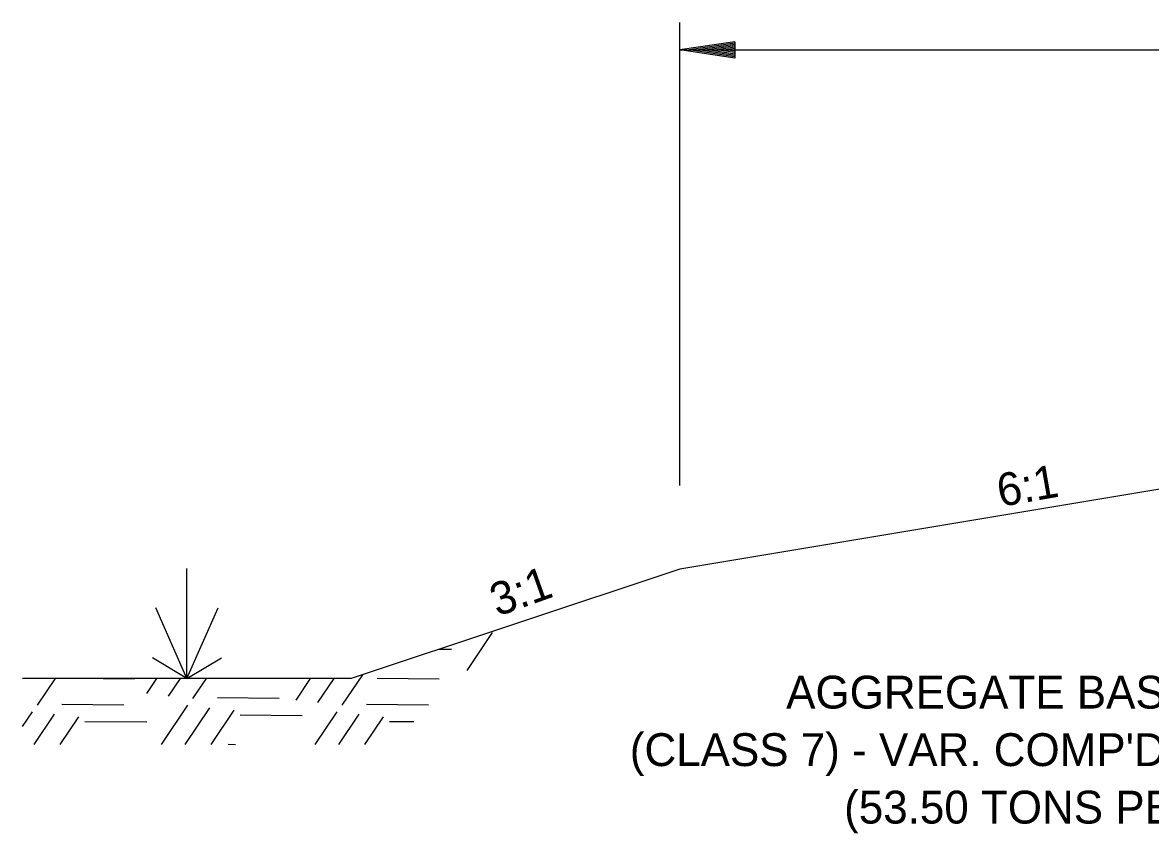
# Model space of a CAD drawing. Extents: x -900 to 15312, y 1857 to 2945.
# Drawn here: x 3634.2 to 3840, y 2382.9 to 2531 of the extents above; entities that cross this region are included whole.
import ezdxf

# ---------------------------------------------------------------- set-up
doc = ezdxf.new("R2010")
doc.units = 0
for name, color, linetype in [('R_Annotation', 7, 'Continuous'), ('R_Dimension', 7, 'Continuous'), ('R_Draft', 7, 'Continuous')]:
    doc.layers.add(name, color=color, linetype=linetype)

msp = doc.modelspace()

# ---------------------------------------------------------------- linework, layer by layer
at = {"layer": 'R_Annotation'}
for p, q in [((3914.16, 2457.89), (3754.16, 2431.22)), ((3754.16, 2431.22), (3694.16, 2411.22)), ((3694.16, 2411.22), (3634.16, 2411.22))]:
    msp.add_line(p, q, dxfattribs=at)
at = {"layer": 'R_Dimension'}
for p, q in [((3754.16, 2446.49), (3754.16, 2531.02)), ((3764.16, 2527.52), (3754.16, 2526.02)), ((3764.16, 2527.27), (3755.83, 2526.02)), ((3764.16, 2527.02), (3757.55, 2526.02)), ((3764.16, 2526.77), (3759.21, 2526.02)), ((3764.16, 2526.51), (3760.91, 2526.02)), ((3764.16, 2526.26), (3762.58, 2526.02)), ((3764.16, 2527.52), (3764.16, 2524.52)), ((3764.16, 2524.52), (3754.16, 2526.02)), ((3754.16, 2526.02), (3954.16, 2526.02)), ((3764.16, 2524.77), (3755.83, 2526.02)), ((3764.16, 2525.03), (3757.55, 2526.02)), ((3764.16, 2525.28), (3759.21, 2526.02)), ((3764.16, 2525.53), (3760.91, 2526.02)), ((3764.16, 2525.79), (3762.58, 2526.02)), ((3715.3, 2412.7), (3719.96, 2419.62)), ((3710.21, 2416.57), (3712.45, 2416.56)), ((3636.9, 2406.35), (3640.19, 2411.22)), ((3648.87, 2411.22), (3654.61, 2411.18)), ((3656.83, 2408.49), (3658.68, 2411.22)), ((3660.82, 2408.02), (3662.98, 2411.22)), ((3665.27, 2407.56), (3667.74, 2411.22)), ((3684.09, 2407.28), (3686.75, 2411.22)), ((3688.07, 2406.82), (3691.05, 2411.22)), ((3692.52, 2406.35), (3696.29, 2411.93)), ((3698.92, 2411.27), (3710.23, 2411.18)), ((3669.72, 2407.75), (3681.03, 2407.65)), ((3634.16, 2402.46), (3635.98, 2405.15)), ((3641.35, 2406.54), (3652.66, 2406.45)), ((3659.52, 2399.2), (3664.34, 2406.35)), ((3663.82, 2399.2), (3668.33, 2405.89)), ((3668.58, 2399.2), (3672.78, 2405.43)), ((3687.58, 2399.2), (3691.6, 2405.15)), ((3696.97, 2406.54), (3708.28, 2406.45)), ((3636.26, 2399.2), (3639.96, 2404.69)), ((3641.03, 2399.2), (3644.41, 2404.22)), ((3645.52, 2403.39), (3656.83, 2403.29)), ((3673.89, 2404.59), (3685.2, 2404.5)), ((3691.88, 2399.2), (3695.58, 2404.69)), ((3696.65, 2399.2), (3700.03, 2404.22)), ((3701.14, 2403.39), (3705.57, 2403.35)), ((3671.67, 2399.21), (3673.02, 2399.2))]:
    msp.add_line(p, q, dxfattribs=at)
at = {"layer": 'R_Draft'}
for q in [(3664.16, 2431.31), (3658.47, 2424.15), (3669.85, 2424.15), (3657.87, 2415.01), (3670.45, 2415.01)]:
    msp.add_line((3664.16, 2411.22), q, dxfattribs=at)

# ---------------------------------------------------------------- texts
at = {"layer": 'R_Annotation'}
for s, rotation, p in [('6:1', 9.9734, (3812.61, 2442.55)), ('3:1', 19.6286, (3720.83, 2422.5))]:
    msp.add_text(s, height=6, rotation=rotation, dxfattribs=at).set_placement(p)
for s, p in [('AGGREGATE BASE COURSE', (3773.55, 2405.74)), ("(CLASS 7) - VAR. COMP'D. DEPTH", (3745.01, 2395.24)), ('(53.50 TONS PER STA.)', (3784.13, 2384.74))]:
    msp.add_text(s, height=6, dxfattribs=at).set_placement(p)

doc.saveas('drawing.dxf')
